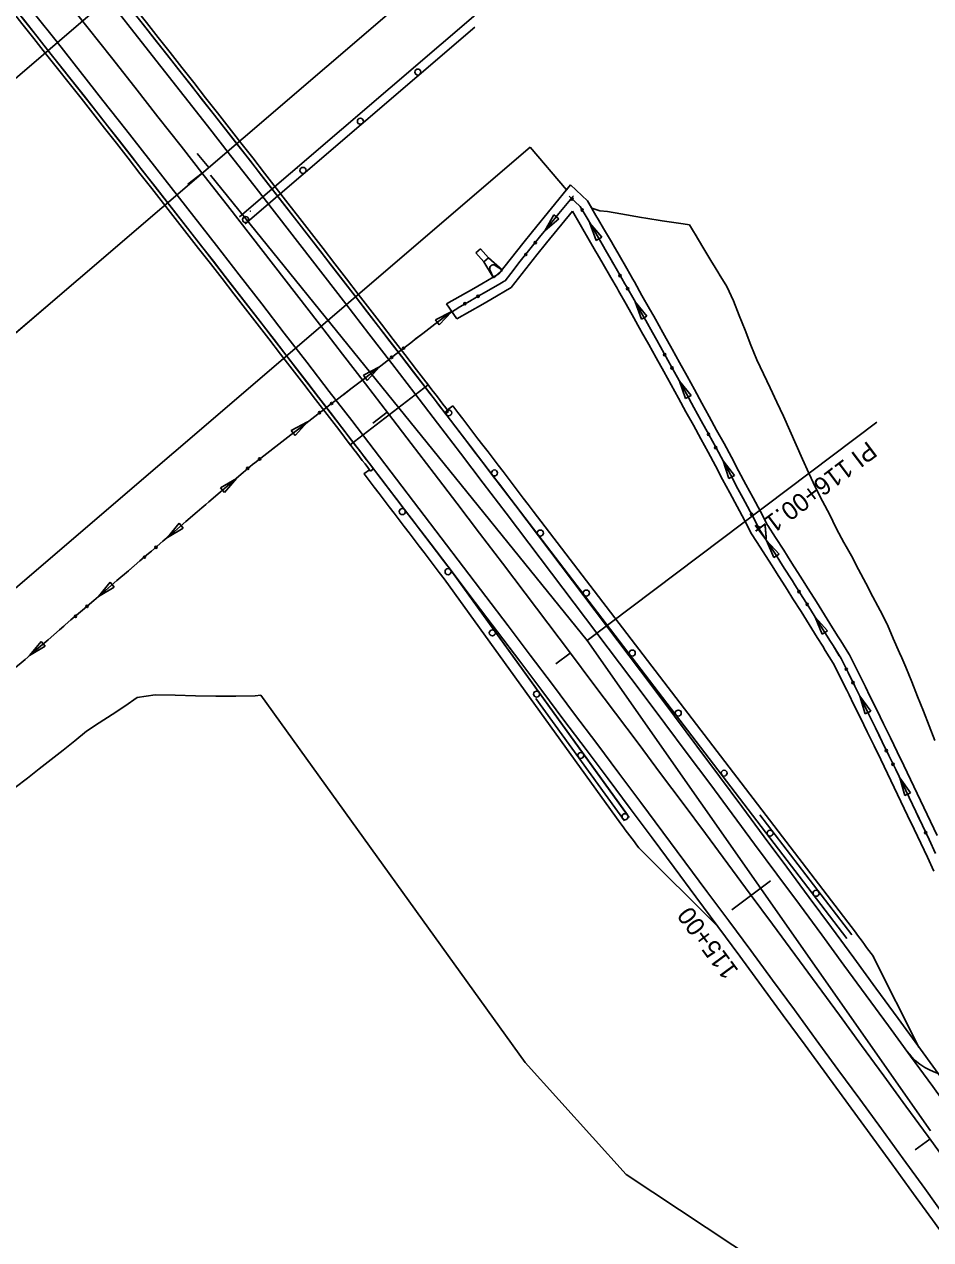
# Model space of a CAD drawing. Extents: x 916431 to 921570, y 1763982 to 1768032.
# Drawn here: x 918993.2 to 919292.9, y 1764755.3 to 1765157.2 of the extents above; entities that cross this region are included whole.
import ezdxf

# ---------------------------------------------------------------- set-up
doc = ezdxf.new("R2010")
doc.units = 0
for name, color, linetype in [('43', 7, 'Continuous'), ('B-Super-Deck', 7, 'Continuous'), ('Default', 7, 'Continuous'), ('R_Conc Ditch Paving', 7, 'Continuous'), ('R_Drainage', 7, 'Continuous'), ('R_Guardrail', 7, 'Continuous'), ('R_Horz Alg', 7, 'Continuous'), ('R_Horz Alg Annot', 7, 'Continuous'), ('R_Horz Alg Stationing', 7, 'Continuous'), ('R_Proposed Const Limits', 7, 'Continuous'), ('R_Proposed Road', 7, 'Continuous'), ('R_Shld', 7, 'Continuous'), ('R_Special Ditch', 7, 'Continuous'), ('S_RDW_PT_SYM', 7, 'Continuous')]:
    doc.layers.add(name, color=color, linetype=linetype)

# ---------------------------------------------------------------- blocks, each defined once
blk = doc.blocks.new('24F_PL')
at = {"layer": '43'}
for p, q in [((0, 0), (-0.1, -0.612)), ((0, 0), (0.2, 0)), ((0.2, 0), (0.3, -0.612)), ((-0.1, -0.612), (-0.011, -0.332)), ((0.3, -0.612), (0.211, -0.332)), ((-0.1, -0.612), (0.3, -0.612))]:
    blk.add_line(p, q, dxfattribs=at)
blk.add_arc((0.1, -0.367), 0.117, 17.5299, 162.4701, dxfattribs=at)

msp = doc.modelspace()

# ---------------------------------------------------------------- linework, layer by layer
at = {"layer": 'B-Super-Deck'}
for p, q in [((919126.81, 1765037.93), (919101.03, 1765018.15)), ((919133.5, 1765029.2), (919132.51, 1765028.44)), ((919107.72, 1765009.42), (919108.71, 1765010.18))]:
    msp.add_line(p, q, dxfattribs=at)
for radius, start, end in [(11474.16, 37.482766, 38.493585), (11475.41, 37.482766, 38.493585), (11442.91, 37.482752, 38.493599), (11444.16, 37.482752, 38.493599), (11474.16, 37.427844, 37.48776), (11475.41, 37.427845, 37.48776), (11444.16, 37.427675, 37.487758), (11442.91, 37.427674, 37.487758)]:
    msp.add_arc((910020.66, 1758054.88), radius, start, end, dxfattribs=at)
at = {"layer": 'Default'}
msp.add_line((918987.45, 1765052.64), (919007.17, 1765069.53), dxfattribs=at)
at = {"layer": 'R_Conc Ditch Paving'}
msp.add_line((919132.88, 1765064.76), (919136.24, 1765059.77), dxfattribs=at)
for points in [[(919150.19, 1765074.72), (919158.06, 1765084.68), (919161.25, 1765088.69), (919173.88, 1765104.07)], [(919295.1, 1764888.92), (919292.91, 1764893.55), (919290.72, 1764898.18), (919288.51, 1764902.81), (919286.3, 1764907.43), (919284.08, 1764912.05), (919281.85, 1764916.66), (919279.61, 1764921.27), (919277.36, 1764925.87), (919275.11, 1764930.47), (919272.84, 1764935.06), (919271.35, 1764938.08), (919270.57, 1764939.65), (919268.29, 1764944.23), (919266.07, 1764948.68), (919265.86, 1764949.01), (919263.2, 1764953.32), (919262.35, 1764954.67), (919260.52, 1764957.61), (919257.85, 1764961.9), (919255.16, 1764966.18), (919252.47, 1764970.46), (919250.58, 1764973.45), (919249.77, 1764974.73), (919247.06, 1764978.99), (919245.57, 1764981.33), (919244.34, 1764983.25), (919241.61, 1764987.5), (919239.08, 1764991.44), (919239.02, 1764991.55), (919236.64, 1764996.05), (919234.25, 1765000.56), (919231.85, 1765005.06), (919229.44, 1765009.55), (919227.02, 1765014.04), (919224.6, 1765018.53), (919222.17, 1765023.01), (919219.72, 1765027.48), (919217.27, 1765031.95), (919214.82, 1765036.41), (919212.37, 1765040.88), (919209.91, 1765045.34), (919207.44, 1765049.8), (919204.96, 1765054.25), (919202.6, 1765058.47), (919202.47, 1765058.7), (919201.35, 1765060.69), (919199.97, 1765063.13), (919197.47, 1765067.57), (919194.95, 1765071.99), (919194.43, 1765072.91), (919192.43, 1765076.41), (919189.89, 1765080.83), (919187.9, 1765084.28), (919187.35, 1765085.24), (919184.8, 1765089.64), (919183.11, 1765092.53), (919182.23, 1765094.03), (919179.45, 1765098.78), (919173.88, 1765104.07)], [(919154.2, 1765070.12), (919162.76, 1765080.95), (919165.91, 1765084.91), (919174.5, 1765095.37)], [(919294.01, 1764877.11), (919291.85, 1764881.73), (919289.67, 1764886.36), (919287.49, 1764890.99), (919285.3, 1764895.61), (919283.1, 1764900.23), (919280.89, 1764904.84), (919278.67, 1764909.44), (919276.45, 1764914.05), (919274.21, 1764918.64), (919271.97, 1764923.23), (919269.72, 1764927.82), (919267.46, 1764932.4), (919265.97, 1764935.42), (919265.2, 1764936.98), (919262.92, 1764941.55), (919260.81, 1764945.78), (919260.74, 1764945.88), (919258.1, 1764950.16), (919257.26, 1764951.51), (919255.43, 1764954.44), (919252.76, 1764958.72), (919250.08, 1764962.99), (919247.39, 1764967.25), (919245.51, 1764970.24), (919244.7, 1764971.51), (919241.99, 1764975.77), (919240.51, 1764978.1), (919239.28, 1764980.02), (919236.56, 1764984.26), (919233.91, 1764988.39), (919233.73, 1764988.72), (919231.34, 1764993.24), (919228.95, 1764997.74), (919226.56, 1765002.23), (919224.15, 1765006.71), (919221.74, 1765011.19), (919219.32, 1765015.67), (919216.9, 1765020.14), (919214.46, 1765024.6), (919212.02, 1765029.06), (919209.56, 1765033.52), (919207.11, 1765037.99), (919204.66, 1765042.44), (919202.2, 1765046.88), (919199.72, 1765051.32), (919197.36, 1765055.54), (919197.24, 1765055.76), (919196.12, 1765057.75), (919194.75, 1765060.19), (919192.25, 1765064.61), (919189.74, 1765069.02), (919189.22, 1765069.93), (919187.22, 1765073.43), (919184.69, 1765077.83), (919182.7, 1765081.28), (919182.16, 1765082.23), (919179.61, 1765086.62), (919177.93, 1765089.51), (919177.05, 1765091), (919174.5, 1765095.37)], [(919132.88, 1765064.76), (919141.84, 1765069.88), (919144.56, 1765071.43), (919150.19, 1765074.72)], [(919136.24, 1765059.77), (919144.81, 1765064.67), (919147.55, 1765066.23), (919154.2, 1765070.12)]]:
    msp.add_lwpolyline(points, dxfattribs=at)
at = {"layer": 'R_Drainage'}
for p, q in [((919144.09, 1765082.98), (919142.56, 1765081.68)), ((919145.15, 1765078.63), (919142.56, 1765081.68)), ((919146.68, 1765079.93), (919144.09, 1765082.98))]:
    msp.add_line(p, q, dxfattribs=at)
at = {"layer": 'R_Guardrail'}
for p, q in [((919066.3, 1765091.22), (919142.25, 1765156.28)), ((919265.22, 1764854.9), (919158.71, 1764994.07)), ((919193.28, 1764894.91), (919134.83, 1764975.91)), ((919191.66, 1764893.74), (919162.4, 1764934.29)), ((919266.81, 1764856.12), (919236.42, 1764895.82))]:
    msp.add_line(p, q, dxfattribs=at)
for points in [[(919067.06, 1765091.87), (919142.25, 1765156.28)], [(919132.76, 1765028.12), (919158.71, 1764994.07), (919265.22, 1764854.9)], [(919192.69, 1764895.73), (919134.83, 1764975.91), (919108.34, 1765010.65)]]:
    msp.add_lwpolyline(points, dxfattribs=at)
for centre in [(919123.37, 1765141.42), (919104.38, 1765125.16), (919085.4, 1765108.89), (919066.41, 1765092.63), (919133.55, 1765028.72), (919148.71, 1765008.84), (919118.2, 1764996.07), (919163.87, 1764988.97), (919133.36, 1764976.19), (919179.07, 1764969.12), (919148, 1764955.96), (919194.26, 1764949.26), (919162.63, 1764935.69), (919209.46, 1764929.41), (919177.25, 1764915.41), (919224.65, 1764909.56), (919191.88, 1764895.14), (919239.85, 1764889.71), (919255.04, 1764869.85)]:
    msp.add_circle(centre, 1, dxfattribs=at)
for radius, start, end in [(11474.16, 37.212076, 37.430826), (11444.16, 37.211926, 37.430676)]:
    msp.add_arc((910020.66, 1758054.88), radius, start, end, dxfattribs=at)
at = {"layer": 'R_Horz Alg'}
msp.add_line((918522.67, 1764654.46), (919661.81, 1765630.35), dxfattribs=at)
msp.add_arc((910020.66, 1758054.88), 11459.16, 34.999167, 38.976944, dxfattribs=at)
at = {"layer": 'R_Horz Alg Annot'}
for q in [(919054.8, 1765107.3), (919292.84, 1764791.28)]:
    msp.add_line((919179.31, 1764953.42), q, dxfattribs=at)
msp.add_lwpolyline([(919179.31, 1764953.42), (919275.16, 1765025.62)], dxfattribs=at)
at = {"layer": 'R_Horz Alg Stationing'}
for points in [[(919050.36, 1765114.43), (919054.27, 1765109.88)], [(919047.33, 1765104.29), (919052.06, 1765107.98)], [(919108.5, 1765025.25), (919113.26, 1765028.9)], [(919168.98, 1764945.68), (919173.77, 1764949.29)], [(919227.16, 1764864.39), (919240.02, 1764873.91)], [(919287.85, 1764784.97), (919292.7, 1764788.49)]]:
    msp.add_lwpolyline(points, dxfattribs=at)
at = {"layer": 'R_Proposed Const Limits'}
for p, q in [((919158.82, 1764813.85), (919071.4, 1764935.3)), ((919192.28, 1764776.88), (919158.82, 1764813.85)), ((919236.36, 1764747.57), (919192.28, 1764776.88))]:
    msp.add_line(p, q, dxfattribs=at)
for points in [[(919173.88, 1765104.07), (919172.55, 1765102.45), (919160.46, 1765116.57)], [(919294.32, 1764920.33), (919292.42, 1764925.19), (919290.52, 1764930.05), (919288.61, 1764934.9), (919286.68, 1764939.75), (919284.72, 1764944.56), (919283.36, 1764947.69), (919282.65, 1764949.3), (919280.57, 1764954.04), (919278.66, 1764958.58), (919278.54, 1764958.81), (919276.2, 1764963.35), (919275.45, 1764964.77), (919273.84, 1764967.88), (919271.48, 1764972.4), (919269.11, 1764976.92), (919266.71, 1764981.43), (919264.97, 1764984.53), (919264.22, 1764985.86), (919261.78, 1764990.33), (919260.57, 1764992.88), (919259.55, 1764994.96), (919257.21, 1764999.51), (919254.98, 1765003.82), (919254.88, 1765004.06), (919252.7, 1765008.73), (919250.56, 1765013.44), (919248.46, 1765018.17), (919246.36, 1765022.9), (919244.23, 1765027.62), (919242.04, 1765032.29), (919239.84, 1765036.95), (919237.62, 1765041.61), (919235.4, 1765046.26), (919233.46, 1765051.12), (919231.55, 1765056.01), (919229.63, 1765060.89), (919227.7, 1765065.77), (919225.52, 1765070.46), (919223.02, 1765074.58), (919222.89, 1765074.8), (919221.7, 1765076.75), (919220.26, 1765079.14), (919217.64, 1765083.49), (919215.01, 1765087.84), (919214.46, 1765088.74), (919213.14, 1765090.91), (919211.09, 1765091.21), (919204.12, 1765092.22), (919198.76, 1765093.1), (919197.28, 1765093.34), (919190.52, 1765094.51), (919186.09, 1765095.3), (919183.58, 1765095.54), (919180.88, 1765096.35), (919179.45, 1765098.78), (919173.88, 1765104.07)], [(918964.92, 1764919.17), (918986.24, 1764901.85), (918990.25, 1764904.86), (918994.26, 1764907.86), (918998.17, 1764910.98), (919002.08, 1764914.11), (919006.06, 1764917.14), (919010, 1764920.23), (919013.83, 1764923.44), (919018.04, 1764926.21), (919022.29, 1764928.94), (919026.46, 1764931.76), (919030.61, 1764934.6), (919036.49, 1764935.42), (919043.14, 1764935.34), (919049.87, 1764935.17), (919056.56, 1764935.05), (919063.18, 1764935), (919069.62, 1764935.18), (919071.4, 1764935.3)]]:
    msp.add_lwpolyline(points, dxfattribs=at)
at = {"layer": 'R_Proposed Road'}
for centre, radius, start, end in [((910020.66, 1758054.88), 11470.16, 34.999167, 38.976944), ((910020.66, 1758054.88), 11448.16, 35.073221, 38.976944), ((919301.31, 1764829.35), 20, 216.1278, 305.9882)]:
    msp.add_arc(centre, radius, start, end, dxfattribs=at)
at = {"layer": 'R_Shld'}
for p, q in [((919202.49, 1765321.13), (918784.8, 1764963.3)), ((919064.35, 1765093.5), (919147.89, 1765165.06)), ((919160.46, 1765116.57), (918775.43, 1764786.72)), ((919134.93, 1765031.04), (919133.14, 1765029.67)), ((919134.93, 1765031.04), (919134.93, 1765031.04)), ((919105.56, 1765008.53), (919107.35, 1765009.89)), ((919105.56, 1765008.53), (919105.56, 1765008.53)), ((919268.04, 1764856.98), (919161.5, 1764996.19)), ((919190.47, 1764892.82), (919132.05, 1764973.79)), ((919222.27, 1764859.23), (919196.44, 1764884.82)), ((919289.06, 1764818.99), (919273.97, 1764848.9))]:
    msp.add_line(p, q, dxfattribs=at)
for radius, start, end in [(11474.16, 34.999167, 38.976944), (11444.16, 35.078536, 38.976944), (11477.66, 37.212076, 37.430826), (11440.66, 37.211926, 37.430676), (11438.66, 36.661926, 36.711926), (11479.66, 36.287076, 36.337076)]:
    msp.add_arc((910020.66, 1758054.88), radius, start, end, dxfattribs=at)
at = {"layer": 'R_Special Ditch'}
for p, q in [((919168.3, 1765094.22), (919165.31, 1765088.91)), ((919165.31, 1765088.91), (919169.94, 1765092.87)), ((919169.94, 1765092.87), (919168.3, 1765094.22)), ((919180.26, 1765091.46), (919182.37, 1765085.74)), ((919184.2, 1765086.81), (919180.26, 1765091.46)), ((919182.37, 1765085.74), (919184.2, 1765086.81)), ((919195.24, 1765065.42), (919197.27, 1765059.68)), ((919199.11, 1765060.72), (919195.24, 1765065.42)), ((919134.56, 1765062.26), (919129.15, 1765059.47)), ((919130.43, 1765057.78), (919134.56, 1765062.26)), ((919197.27, 1765059.68), (919199.11, 1765060.72)), ((919129.15, 1765059.47), (919130.43, 1765057.78)), ((919110.74, 1765043.96), (919105.35, 1765041.12)), ((919106.65, 1765039.45), (919110.74, 1765043.96)), ((919105.35, 1765041.12), (919106.65, 1765039.45)), ((919209.87, 1765039.19), (919211.83, 1765033.42)), ((919213.69, 1765034.44), (919209.87, 1765039.19)), ((919211.83, 1765033.42), (919213.69, 1765034.44)), ((919086.89, 1765025.7), (919081.49, 1765022.87)), ((919082.78, 1765021.2), (919086.89, 1765025.7)), ((919081.49, 1765022.87), (919082.78, 1765021.2)), ((919224.27, 1765012.83), (919226.18, 1765007.04)), ((919228.05, 1765008.04), (919224.27, 1765012.83)), ((919226.18, 1765007.04), (919228.05, 1765008.04)), ((919063.35, 1765007.05), (919058.11, 1765003.95)), ((919058.11, 1765003.95), (919059.48, 1765002.34)), ((919059.48, 1765002.34), (919063.35, 1765007.05)), ((919044.44, 1764992.24), (919040.57, 1764987.53)), ((919045.81, 1764990.63), (919044.44, 1764992.24)), ((919040.57, 1764987.53), (919045.81, 1764990.63)), ((919238.7, 1764986.49), (919241.04, 1764980.87)), ((919242.83, 1764982.01), (919238.7, 1764986.49)), ((919241.04, 1764980.87), (919242.83, 1764982.01)), ((919021.63, 1764972.7), (919017.76, 1764967.99)), ((919017.76, 1764967.99), (919023, 1764971.09)), ((919023, 1764971.09), (919021.63, 1764972.7)), ((919254.79, 1764961.13), (919257.07, 1764955.48)), ((919258.87, 1764956.6), (919254.79, 1764961.13)), ((919257.07, 1764955.48), (919258.87, 1764956.6)), ((918998.81, 1764953.15), (918994.95, 1764948.45)), ((918994.95, 1764948.45), (919000.19, 1764951.55)), ((919000.19, 1764951.55), (918998.81, 1764953.15)), ((919269.53, 1764934.99), (919271.23, 1764929.15)), ((919273.13, 1764930.08), (919269.53, 1764934.99)), ((919271.23, 1764929.15), (919273.13, 1764930.08)), ((919282.7, 1764908), (919284.34, 1764902.13)), ((919286.25, 1764903.04), (919282.7, 1764908)), ((919284.34, 1764902.13), (919286.25, 1764903.04))]:
    msp.add_line(p, q, dxfattribs=at)
for points in [[(919152.2, 1765072.42), (919154.09, 1765074.82), (919157.25, 1765078.82), (919160.41, 1765082.82), (919163.58, 1765086.8), (919166.8, 1765090.72), (919170.02, 1765094.65), (919171.68, 1765096.67), (919173.25, 1765098.57), (919174.46, 1765100.05), (919174.53, 1765100.14), (919174.8, 1765100.52)], [(919174.8, 1765100.52), (919174.53, 1765100.14), (919174.46, 1765100.05), (919173.25, 1765098.57), (919171.68, 1765096.67), (919170.02, 1765094.65), (919166.8, 1765090.72), (919165.31, 1765088.91)], [(919294.57, 1764883), (919292.39, 1764887.64), (919290.2, 1764892.27), (919288.01, 1764896.9), (919285.81, 1764901.52), (919283.59, 1764906.14), (919281.38, 1764910.75), (919279.15, 1764915.35), (919276.91, 1764919.96), (919274.67, 1764924.55), (919272.41, 1764929.14), (919270.15, 1764933.73), (919268.66, 1764936.75), (919267.88, 1764938.31), (919265.61, 1764942.89), (919263.44, 1764947.23), (919263.3, 1764947.44), (919260.65, 1764951.74), (919259.81, 1764953.09), (919257.98, 1764956.03), (919255.3, 1764960.31), (919252.62, 1764964.58), (919249.93, 1764968.85), (919248.04, 1764971.84), (919247.23, 1764973.12), (919244.53, 1764977.38), (919243.04, 1764979.71), (919241.81, 1764981.63), (919239.09, 1764985.88), (919236.49, 1764989.91), (919236.37, 1764990.14), (919233.99, 1764994.64), (919231.6, 1764999.15), (919229.2, 1765003.64), (919226.8, 1765008.13), (919224.38, 1765012.62), (919221.96, 1765017.1), (919219.53, 1765021.57), (919217.09, 1765026.04), (919214.65, 1765030.51), (919212.19, 1765034.97), (919209.74, 1765039.43), (919207.28, 1765043.89), (919204.82, 1765048.34), (919202.34, 1765052.79), (919199.98, 1765057), (919199.86, 1765057.23), (919198.73, 1765059.22), (919197.36, 1765061.66), (919194.86, 1765066.09), (919192.35, 1765070.51), (919191.82, 1765071.42), (919189.82, 1765074.92), (919187.29, 1765079.33), (919185.3, 1765082.78), (919184.75, 1765083.73), (919182.2, 1765088.13), (919180.52, 1765091.02), (919179.64, 1765092.52), (919177.07, 1765096.9), (919173.38, 1765100.41)], [(919187.78, 1765078.48), (919187.29, 1765079.33), (919185.3, 1765082.78), (919184.75, 1765083.73), (919182.2, 1765088.13), (919180.52, 1765091.02), (919180.26, 1765091.46)], [(919155.93, 1765077.15), (919154.09, 1765074.82), (919152.2, 1765072.42)], [(919155.96, 1765077.18), (919155.93, 1765077.15)], [(919187.8, 1765078.45), (919187.78, 1765078.48)], [(919051.96, 1764997.29), (919053.24, 1764998.38), (919054.24, 1764999.24), (919058.04, 1765002.49), (919061.83, 1765005.75), (919065.63, 1765009), (919067.15, 1765010.3), (919067.91, 1765010.95), (919068.67, 1765011.6), (919069.46, 1765012.21), (919073.42, 1765015.28), (919077.38, 1765018.35), (919081.33, 1765021.41), (919085.3, 1765024.47), (919089.28, 1765027.51), (919093.26, 1765030.55), (919094.86, 1765031.77), (919097.24, 1765033.59), (919101.22, 1765036.62), (919105.2, 1765039.66), (919109.16, 1765042.73), (919113.12, 1765045.79), (919117.08, 1765048.86), (919121.04, 1765051.92), (919122.32, 1765052.92), (919125, 1765054.98), (919128.98, 1765058.01), (919132.97, 1765061.05), (919137.21, 1765063.78), (919141.28, 1765066.1), (919141.6, 1765066.28), (919141.63, 1765066.31), (919143.33, 1765067.27), (919146.06, 1765068.83), (919150.44, 1765071.39), (919151.61, 1765072.08), (919151.93, 1765072.26), (919152.2, 1765072.42)], [(919147.62, 1765069.74), (919150.44, 1765071.39), (919151.61, 1765072.08), (919151.93, 1765072.26), (919152.2, 1765072.42)], [(919147.58, 1765069.72), (919147.62, 1765069.74)], [(919202.59, 1765052.34), (919202.34, 1765052.79), (919199.98, 1765057), (919199.86, 1765057.23), (919198.73, 1765059.22), (919197.36, 1765061.66), (919195.24, 1765065.42)], [(919122.64, 1765053.16), (919125, 1765054.98), (919128.98, 1765058.01), (919132.97, 1765061.05), (919134.65, 1765062.13)], [(919122.61, 1765053.13), (919122.64, 1765053.16)], [(919202.61, 1765052.31), (919202.59, 1765052.34)], [(919098.85, 1765034.81), (919101.22, 1765036.62), (919105.2, 1765039.66), (919109.16, 1765042.73), (919110.74, 1765043.96)], [(919217.09, 1765026.04), (919217.09, 1765026.04), (919214.65, 1765030.51), (919212.19, 1765034.97), (919209.87, 1765039.19)], [(919098.82, 1765034.79), (919098.85, 1765034.81)], [(919075.02, 1765016.52), (919077.38, 1765018.35), (919081.33, 1765021.41), (919085.3, 1765024.47), (919086.89, 1765025.69)], [(919217.11, 1765026.01), (919217.09, 1765026.04)], [(919074.99, 1765016.5), (919075.02, 1765016.52)], [(919231.36, 1764999.61), (919229.2, 1765003.64), (919226.8, 1765008.13), (919224.38, 1765012.62), (919224.27, 1765012.83)], [(919051.96, 1764997.29), (919053.24, 1764998.38), (919054.24, 1764999.24), (919058.04, 1765002.49), (919061.83, 1765005.75), (919063.35, 1765007.05)], [(919231.37, 1764999.57), (919231.36, 1764999.6)], [(918989.69, 1764943.94), (918993.48, 1764947.19), (918997.28, 1764950.45), (919001.08, 1764953.7), (919004.88, 1764956.95), (919008.67, 1764960.21), (919012.47, 1764963.46), (919016.27, 1764966.71), (919020.06, 1764969.96), (919023.86, 1764973.22), (919027.66, 1764976.47), (919031.46, 1764979.72), (919034.3, 1764982.16), (919035.25, 1764982.98), (919039.05, 1764986.23), (919042.85, 1764989.48), (919046.64, 1764992.74), (919050.44, 1764995.99), (919051.96, 1764997.29)], [(919051.96, 1764997.29), (919050.44, 1764995.99), (919046.64, 1764992.74), (919042.85, 1764989.48), (919040.57, 1764987.53)], [(919246.77, 1764973.85), (919244.53, 1764977.38), (919243.04, 1764979.71), (919241.81, 1764981.63), (919239.09, 1764985.88), (919238.7, 1764986.49)], [(919029.15, 1764977.75), (919027.66, 1764976.47), (919023.86, 1764973.22), (919020.06, 1764969.96), (919017.76, 1764967.99)], [(919029.18, 1764977.77), (919029.15, 1764977.75)], [(919246.79, 1764973.82), (919246.77, 1764973.85)], [(919262.72, 1764948.39), (919260.65, 1764951.74), (919259.81, 1764953.09), (919257.98, 1764956.03), (919255.3, 1764960.31), (919254.79, 1764961.13)], [(919006.34, 1764958.2), (919004.88, 1764956.95), (919001.08, 1764953.7), (918997.28, 1764950.45), (918994.95, 1764948.45)], [(919006.37, 1764958.23), (919006.34, 1764958.2)], [(919262.74, 1764948.36), (919262.72, 1764948.39)], [(919276.14, 1764921.53), (919274.67, 1764924.55), (919272.41, 1764929.14), (919270.15, 1764933.73), (919269.53, 1764934.99)], [(919276.16, 1764921.5), (919276.14, 1764921.53)], [(919289.16, 1764894.46), (919288.01, 1764896.9), (919285.81, 1764901.52), (919283.59, 1764906.14), (919282.7, 1764908)], [(919289.18, 1764894.43), (919289.16, 1764894.46)]]:
    msp.add_lwpolyline(points, dxfattribs=at)
for centre in [(919174.36, 1765099.43), (919177.7, 1765095.76), (919162.19, 1765085), (919159.07, 1765081.07), (919190.25, 1765074.11), (919143.25, 1765067.27), (919192.73, 1765069.75), (919138.9, 1765064.78), (919118.64, 1765050.11), (919205, 1765047.94), (919114.68, 1765047.05), (919207.43, 1765043.56), (919094.84, 1765031.8), (919090.85, 1765028.76), (919219.47, 1765021.61), (919221.86, 1765017.21), (919071.03, 1765013.47), (919067.13, 1765010.33), (919233.68, 1764995.15), (919236.02, 1764990.72), (919036.79, 1764984.25), (919032.99, 1764980.99), (919249.42, 1764969.59), (919013.98, 1764964.7), (919252.1, 1764965.35), (919010.17, 1764961.44), (919265.04, 1764943.95), (919267.27, 1764939.46), (919278.31, 1764917), (919280.49, 1764912.49), (919291.28, 1764889.91)]:
    msp.add_circle(centre, 0.375, dxfattribs=at)
at = {"layer": 'S_RDW_PT_SYM'}
for points in [[(919083.5, 1765109.78), (919083.5, 1765109.83), (919083.5, 1765109.78), (919083.45, 1765109.78), (919083.5, 1765109.78), (919083.5, 1765109.73), (919083.5, 1765109.78), (919083.55, 1765109.78)], [(919068.03, 1765095.41), (919068.03, 1765095.46), (919068.03, 1765095.41), (919067.98, 1765095.41), (919068.03, 1765095.41), (919068.03, 1765095.36), (919068.03, 1765095.41), (919068.08, 1765095.41)]]:
    msp.add_lwpolyline(points, dxfattribs=at)

# ---------------------------------------------------------------- block references
at = {"layer": 'R_Drainage', "xscale": 10.000000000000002, "yscale": 10.000000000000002, "rotation": 40.32021161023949}
msp.add_blockref('24F_PL', (919145.15, 1765078.63), dxfattribs=at)

# ---------------------------------------------------------------- texts
at = {"layer": 'R_Horz Alg Annot'}
msp.add_text('PI 116+00.14', height=6, rotation=216.9881, dxfattribs=at).set_placement((919272.17, 1765019.62))
at = {"layer": 'R_Horz Alg Stationing'}
msp.add_text('115+00', height=6, rotation=126.4882, dxfattribs=at).set_placement((919229.61, 1764844.26))

doc.saveas('drawing.dxf')
